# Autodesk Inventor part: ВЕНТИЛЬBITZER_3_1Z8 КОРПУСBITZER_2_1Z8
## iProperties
Created: 2011-02
Part Number: ВЕНТИЛЬBITZER_3_1Z8 КОРПУСBITZER_2_1Z8
Document SubType Name: Modeling
Designer: Чернышев Юрий
Mass: 2189.99 g
Surface Area: 1545.47 cm^2
Volume: 2189.99 cm^3
Density: 1 g/cm^3
Author: Чернышев Юрий
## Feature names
1. ExtrusionBlind1
2. ExtrusionBlind2
3. ExtrusionBlind5
4. ExtrusionBlind6
5. ExtrusionBlind7
6. RevolutionAngle1
7. Fillet3
8. Hole1
9. Hole6
10. Hole7
11. Hole8
12. Hole9
13. Hole10
14. Hole11
15. Hole12
16. Hole13
17. ExtrusionBlind8
18. Hole14
